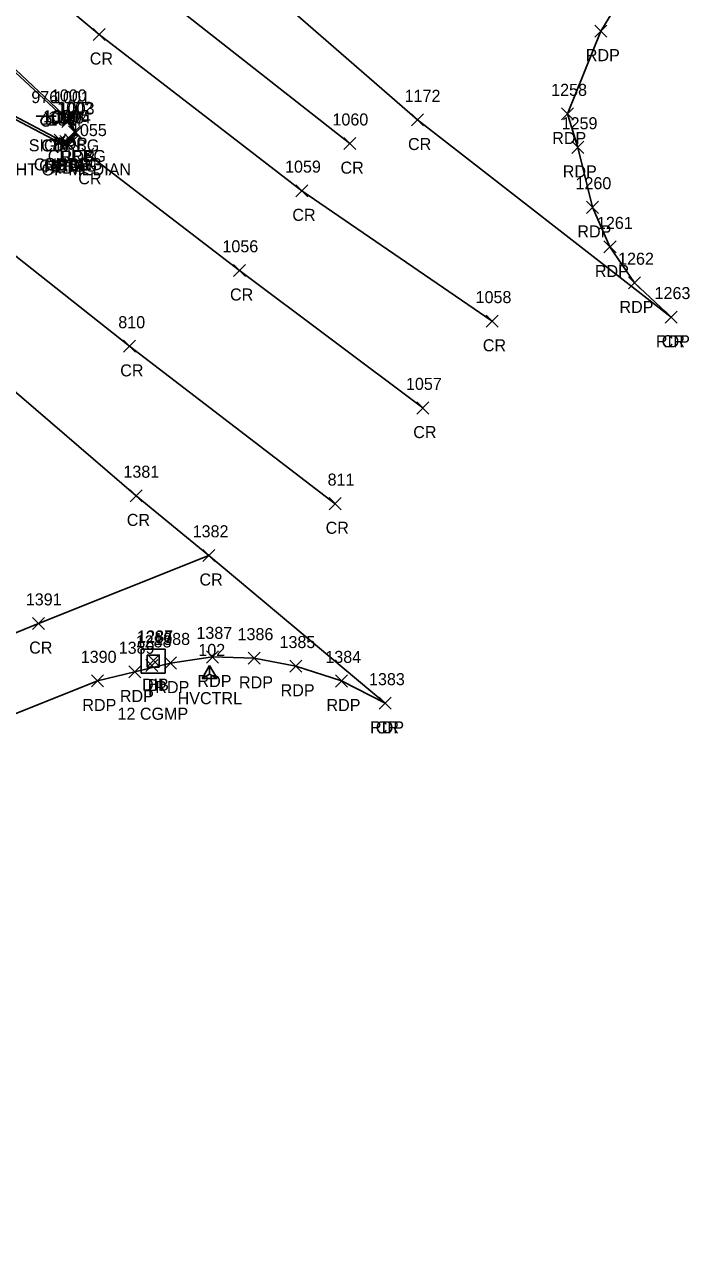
# Model space of a CAD drawing. Extents: x 1688195 to 1692013, y 424605 to 441234.
# Drawn here: x 1691903 to 1692013.4, y 439041.4 to 439243.2 of the extents above; entities that cross this region are included whole.
import ezdxf

# ---------------------------------------------------------------- set-up
doc = ezdxf.new("R2010")
doc.units = 0
for name, color, linetype in [('C_A', 7, 'Continuous'), ('C_I', 7, 'Continuous'), ('CPSM', 7, 'Continuous'), ('D_A', 7, 'Continuous'), ('D_C', 7, 'Continuous'), ('D_I', 7, 'Continuous'), ('D_TIC', 7, 'Continuous'), ('DS', 7, 'Continuous'), ('P_A', 7, 'Continuous'), ('P_I', 7, 'Continuous'), ('P_TIC', 7, 'Continuous'), ('PET', 7, 'Continuous'), ('PRC', 7, 'Continuous'), ('R_A', 7, 'Continuous'), ('R_I', 7, 'Continuous'), ('R_TIC', 7, 'Continuous'), ('RC', 7, 'Continuous'), ('S_A', 7, 'Continuous'), ('S_C', 7, 'Continuous'), ('S_I', 7, 'Continuous'), ('SSGN', 7, 'Continuous')]:
    doc.layers.add(name, color=color, linetype=linetype)

msp = doc.modelspace()

# ---------------------------------------------------------------- linework, layer by layer
at = {"layer": 'CPSM'}
for p, q in [((1691932.47, 439134.69), (1691933.72, 439136.85)), ((1691932.47, 439134.69), (1691933.72, 439136.85)), ((1691932.47, 439134.69), (1691933.72, 439136.85)), ((1691932.47, 439134.69), (1691933.72, 439136.85)), ((1691934.97, 439134.69), (1691933.72, 439136.85)), ((1691933.72, 439135.41), (1691933.72, 439136.85)), ((1691934.97, 439134.69), (1691933.72, 439136.85)), ((1691933.72, 439135.41), (1691933.72, 439136.85)), ((1691934.97, 439134.69), (1691933.72, 439136.85)), ((1691933.72, 439135.41), (1691933.72, 439136.85)), ((1691934.97, 439134.69), (1691933.72, 439136.85)), ((1691933.72, 439135.41), (1691933.72, 439136.85)), ((1691932.47, 439134.69), (1691933.72, 439135.41)), ((1691932.47, 439134.69), (1691933.72, 439135.41)), ((1691932.47, 439134.69), (1691933.72, 439135.41)), ((1691932.47, 439134.69), (1691933.72, 439135.41)), ((1691932.47, 439134.69), (1691934.97, 439134.69)), ((1691932.47, 439134.69), (1691934.97, 439134.69)), ((1691932.47, 439134.69), (1691934.97, 439134.69)), ((1691932.47, 439134.69), (1691934.97, 439134.69)), ((1691933.72, 439135.41), (1691933.72, 439135.41)), ((1691933.72, 439135.41), (1691934.97, 439134.69)), ((1691933.72, 439135.41), (1691933.72, 439135.41)), ((1691933.72, 439135.41), (1691934.97, 439134.69)), ((1691933.72, 439135.41), (1691933.72, 439135.41)), ((1691933.72, 439135.41), (1691934.97, 439134.69)), ((1691933.72, 439135.41), (1691933.72, 439135.41)), ((1691933.72, 439135.41), (1691934.97, 439134.69))]:
    msp.add_line(p, q, dxfattribs=at)
at = {"layer": 'D_TIC'}
for points in [[(1691923.39, 439136.66), (1691925.39, 439138.66)], [(1691925.39, 439136.66), (1691923.39, 439138.66)], [(1691923.14, 439135.83), (1691925.14, 439137.83)], [(1691925.14, 439135.83), (1691923.14, 439137.83)]]:
    msp.add_lwpolyline(points, dxfattribs=at)
at = {"layer": 'DS'}
for p, q in [((1691922.36, 439139.56), (1691926.36, 439139.56)), ((1691922.36, 439135.56), (1691922.36, 439139.56)), ((1691926.36, 439139.56), (1691926.36, 439135.56)), ((1691923.36, 439136.56), (1691923.36, 439138.56)), ((1691923.36, 439138.56), (1691925.36, 439138.56)), ((1691924.36, 439137.57), (1691924.36, 439137.57)), ((1691924.36, 439137.57), (1691924.36, 439137.57)), ((1691925.36, 439138.56), (1691925.36, 439136.56)), ((1691926.36, 439135.56), (1691922.36, 439135.56)), ((1691925.36, 439136.56), (1691923.36, 439136.56))]:
    msp.add_line(p, q, dxfattribs=at)
at = {"layer": 'P_TIC'}
for points in [[(1691914.39, 439240.55), (1691916.39, 439242.55)], [(1691916.39, 439240.55), (1691914.39, 439242.55)], [(1691997.71, 439241.11), (1691999.71, 439243.11)], [(1691999.71, 439241.11), (1691997.71, 439243.11)], [(1691909.3, 439226.43), (1691911.3, 439228.43)], [(1691911.3, 439226.43), (1691909.3, 439228.43)], [(1691967.23, 439226.36), (1691969.23, 439228.36)], [(1691969.23, 439226.36), (1691967.23, 439228.36)], [(1691992.13, 439227.35), (1691994.13, 439229.35)], [(1691994.13, 439227.35), (1691992.13, 439229.35)], [(1691910.52, 439224.27), (1691912.52, 439226.27)], [(1691912.52, 439224.27), (1691910.52, 439226.27)], [(1691907.76, 439222.6), (1691909.76, 439224.6)], [(1691909.76, 439222.6), (1691907.76, 439224.6)], [(1691908.81, 439222.42), (1691910.81, 439224.42)], [(1691910.81, 439222.42), (1691908.81, 439224.42)], [(1691909.89, 439222.79), (1691911.89, 439224.79)], [(1691911.89, 439222.79), (1691909.89, 439224.79)], [(1691956.02, 439222.44), (1691958.02, 439224.44)], [(1691958.02, 439222.44), (1691956.02, 439224.44)], [(1691993.88, 439221.81), (1691995.88, 439223.81)], [(1691995.88, 439221.81), (1691993.88, 439223.81)], [(1691912.48, 439220.68), (1691914.48, 439222.68)], [(1691914.48, 439220.68), (1691912.48, 439222.68)], [(1691948.03, 439214.61), (1691950.03, 439216.61)], [(1691950.03, 439214.61), (1691948.03, 439216.61)], [(1691996.3, 439211.86), (1691998.3, 439213.86)], [(1691998.3, 439211.86), (1691996.3, 439213.86)], [(1691999.21, 439205.28), (1692001.21, 439207.28)], [(1692001.21, 439205.28), (1691999.21, 439207.28)], [(1691937.67, 439201.39), (1691939.67, 439203.39)], [(1691939.67, 439201.39), (1691937.67, 439203.39)], [(1692003.29, 439199.33), (1692005.29, 439201.33)], [(1692005.29, 439199.33), (1692003.29, 439201.33)], [(1692009.35, 439193.63), (1692011.35, 439195.63)], [(1692011.35, 439193.63), (1692009.35, 439195.63)], [(1692009.35, 439193.63), (1692011.35, 439195.63)], [(1692011.35, 439193.63), (1692009.35, 439195.63)], [(1691979.66, 439192.96), (1691981.66, 439194.96)], [(1691981.66, 439192.96), (1691979.66, 439194.96)], [(1691919.44, 439188.8), (1691921.44, 439190.8)], [(1691921.44, 439188.8), (1691919.44, 439190.8)], [(1691968.11, 439178.56), (1691970.11, 439180.56)], [(1691970.11, 439178.56), (1691968.11, 439180.56)], [(1691920.53, 439163.99), (1691922.53, 439165.99)], [(1691922.53, 439163.99), (1691920.53, 439165.99)], [(1691953.55, 439162.68), (1691955.55, 439164.68)], [(1691955.55, 439162.68), (1691953.55, 439164.68)], [(1691932.61, 439154.1), (1691934.61, 439156.1)], [(1691934.61, 439154.1), (1691932.61, 439156.1)], [(1691932.61, 439154.1), (1691934.61, 439156.1)], [(1691934.61, 439154.1), (1691932.61, 439156.1)], [(1691904.33, 439142.8), (1691906.33, 439144.8)], [(1691906.33, 439142.8), (1691904.33, 439144.8)], [(1691933.22, 439137.24), (1691935.22, 439139.24)], [(1691935.22, 439137.24), (1691933.22, 439139.24)], [(1691940.11, 439137.03), (1691942.11, 439139.03)], [(1691942.11, 439137.03), (1691940.11, 439139.03)], [(1691920.33, 439134.77), (1691922.33, 439136.77)], [(1691922.33, 439134.77), (1691920.33, 439136.77)], [(1691926.22, 439136.24), (1691928.22, 439138.24)], [(1691928.22, 439136.24), (1691926.22, 439138.24)], [(1691947.02, 439135.72), (1691949.02, 439137.72)], [(1691949.02, 439135.72), (1691947.02, 439137.72)], [(1691914.1, 439133.27), (1691916.1, 439135.27)], [(1691916.1, 439133.27), (1691914.1, 439135.27)], [(1691954.64, 439133.26), (1691956.64, 439135.26)], [(1691956.64, 439133.26), (1691954.64, 439135.26)], [(1691961.88, 439129.56), (1691963.88, 439131.56)], [(1691963.88, 439129.56), (1691961.88, 439131.56)], [(1691961.88, 439129.56), (1691963.88, 439131.56)], [(1691963.88, 439129.56), (1691961.88, 439131.56)]]:
    msp.add_lwpolyline(points, dxfattribs=at)
at = {"layer": 'PET'}
for points in [[(1691800.95, 439315.05), (1691800.71, 439316.53), (1691801.54, 439317.59), (1691803.01, 439317.75), (1691817.06, 439309.7), (1691828.51, 439300.65), (1691844.68, 439285.42), (1691865.17, 439267.39), (1691884.85, 439250.83), (1691897.53, 439239.42), (1691910.3, 439227.43), (1691911.52, 439225.27), (1691910.89, 439223.79), (1691909.81, 439223.42), (1691908.76, 439223.6), (1691890.09, 439233.4), (1691870.38, 439245.17), (1691862.38, 439250.39), (1691860.03, 439251.8), (1691851, 439258.94), (1691829.1, 439279.04), (1691821.39, 439286.91), (1691810.78, 439300.43)], [(1692007.49, 439254.05), (1692002.68, 439248.67), (1691998.71, 439242.11), (1691993.13, 439228.35), (1691994.88, 439222.81), (1691997.3, 439212.86), (1692000.21, 439206.28), (1692004.29, 439200.33), (1692010.35, 439194.63)], [(1691962.88, 439130.56), (1691955.64, 439134.26), (1691948.02, 439136.72), (1691941.11, 439138.03), (1691934.22, 439138.24), (1691927.22, 439137.24), (1691921.33, 439135.77), (1691915.1, 439134.27), (1691873.49, 439117.66), (1691865.77, 439114.89), (1691827.16, 439101.41), (1691792.77, 439088.6), (1691761.14, 439076.62), (1691734.19, 439066.23), (1691708.14, 439056.57), (1691672.86, 439042.9), (1691649.54, 439032.89)]]:
    msp.add_lwpolyline(points, dxfattribs=at)
at = {"layer": 'PRC'}
for points in [[(1691980.66, 439193.96), (1691949.03, 439215.61), (1691915.39, 439241.55), (1691887.2, 439265.05), (1691850.38, 439298.07), (1691824.99, 439321.73), (1691796.94, 439350.89), (1691771.5, 439379.22), (1691742.05, 439414.41)], [(1691713.18, 439386.48), (1691737.31, 439357.71), (1691761.17, 439330.74), (1691784.31, 439305.52), (1691812.13, 439278.2), (1691838.3, 439254.51), (1691867.44, 439230.25), (1691889.26, 439214.41), (1691920.44, 439189.8), (1691954.55, 439163.68)], [(1691957.02, 439223.44), (1691923.55, 439249.72), (1691894.35, 439275.35), (1691862.96, 439302.59), (1691832.42, 439330.49), (1691805.17, 439357.5)], [(1691939.54, 439252.36), (1691968.23, 439227.36), (1692010.35, 439194.63)], [(1691913.48, 439221.68), (1691938.67, 439202.39), (1691969.11, 439179.56)], [(1691888.13, 439193.66), (1691921.53, 439164.99), (1691933.61, 439155.1), (1691905.33, 439143.8), (1691864.7, 439127.18), (1691822.78, 439112.3), (1691787.26, 439099.58), (1691756.92, 439088.3), (1691729.19, 439077.85), (1691704.03, 439068.3), (1691667.7, 439053.5), (1691645.71, 439043.49), (1691628.46, 439034.88), (1691608.73, 439022.92), (1691585.22, 439006.39), (1691574.92, 438998.75), (1691559.84, 438985.93), (1691543.5, 438970.76), (1691518.61, 438946.02), (1691478.27, 438903.21), (1691447.81, 438870), (1691426.94, 438847.45)], [(1691933.61, 439155.1), (1691962.88, 439130.56)]]:
    msp.add_lwpolyline(points, dxfattribs=at)
at = {"layer": 'R_TIC'}
for points in [[(1691909.16, 439226.13), (1691911.16, 439228.13)], [(1691911.16, 439226.13), (1691909.16, 439228.13)], [(1691910.27, 439224.37), (1691912.27, 439226.37)], [(1691912.27, 439224.37), (1691910.27, 439226.37)], [(1691907.93, 439222.98), (1691909.93, 439224.98)], [(1691909.93, 439222.98), (1691907.93, 439224.98)], [(1691908.84, 439222.78), (1691910.84, 439224.78)], [(1691910.84, 439222.78), (1691908.84, 439224.78)], [(1691909.65, 439223.03), (1691911.65, 439225.03)], [(1691911.65, 439223.03), (1691909.65, 439225.03)]]:
    msp.add_lwpolyline(points, dxfattribs=at)
at = {"layer": 'RC'}
msp.add_lwpolyline([(1691801.25, 439315.04), (1691801.11, 439316.33), (1691801.76, 439317.38), (1691802.82, 439317.35), (1691816.87, 439309.41), (1691828.25, 439300.3), (1691844.42, 439285.11), (1691865.02, 439267.12), (1691884.74, 439250.47), (1691897.46, 439238.93), (1691910.16, 439227.13), (1691911.27, 439225.37), (1691910.65, 439224.03), (1691909.84, 439223.78), (1691908.93, 439223.98), (1691890.41, 439233.73), (1691870.59, 439245.45), (1691863.21, 439250.36), (1691862.38, 439250.39)], dxfattribs=at)
at = {"layer": 'SSGN'}
for p, q in [((1691904.91, 439228.01), (1691908.24, 439228.01)), ((1691906.55, 439227.17), (1691906.55, 439227.17))]:
    msp.add_line(p, q, dxfattribs=at)
msp.add_circle((1691906.55, 439227.17), 0.833, dxfattribs=at)

# ---------------------------------------------------------------- texts
at = {"layer": 'C_A'}
msp.add_text('HVCTRL', height=2, dxfattribs=at).set_placement((1691928.41, 439130.41))
msp.add_text('HVCTRL', height=2, dxfattribs=at).set_placement((1691928.41, 439130.41))
msp.add_text('HVCTRL', height=2, dxfattribs=at).set_placement((1691928.41, 439130.41))
msp.add_text('HVCTRL', height=2, dxfattribs=at).set_placement((1691928.41, 439130.41))
at = {"layer": 'C_I'}
msp.add_text('102', height=2, dxfattribs=at).set_placement((1691931.85, 439138.41))
msp.add_text('102', height=2, dxfattribs=at).set_placement((1691931.85, 439138.41))
msp.add_text('102', height=2, dxfattribs=at).set_placement((1691931.85, 439138.41))
msp.add_text('102', height=2, dxfattribs=at).set_placement((1691931.85, 439138.41))
at = {"layer": 'D_A'}
for s, p in [('DIB', (1691922.5, 439132.66)), ('DI', (1691923.42, 439132.57)), ('P', (1691923.52, 439131.83))]:
    msp.add_text(s, height=2, dxfattribs=at).set_placement(p)
at = {"layer": 'D_C'}
msp.add_text('12 CGMP', height=2, dxfattribs=at).set_placement((1691918.43, 439127.83))
at = {"layer": 'D_I'}
for s, p in [('1287', (1691921.7, 439140.66)), ('1288', (1691921.45, 439139.83)), ('1286', (1691921.61, 439140.57))]:
    msp.add_text(s, height=2, dxfattribs=at).set_placement(p)
at = {"layer": 'P_A'}
for s, p in [('CR', (1691913.82, 439236.55)), ('RDP', (1691996.2, 439237.11)), ('RDP', (1691907.79, 439222.43)), ('CR', (1691966.67, 439222.36)), ('RDP', (1691990.62, 439223.35)), ('RDP', (1691909.01, 439220.27)), ('RDP', (1691906.25, 439218.6)), ('RDP', (1691907.3, 439218.42)), ('RDP', (1691908.38, 439218.79)), ('CR', (1691955.46, 439218.44)), ('RDP', (1691992.37, 439217.81)), ('CR', (1691911.91, 439216.68)), ('CR', (1691947.46, 439210.61)), ('RDP', (1691994.79, 439207.86)), ('RDP', (1691997.7, 439201.28)), ('CR', (1691937.11, 439197.39)), ('RDP', (1692001.78, 439195.33)), ('RDP', (1692007.84, 439189.63)), ('CR', (1692008.79, 439189.63)), ('CR', (1691979.09, 439188.96)), ('CR', (1691918.88, 439184.8)), ('CR', (1691967.54, 439174.56)), ('CR', (1691919.97, 439159.99)), ('CR', (1691952.99, 439158.68)), ('CR', (1691932.04, 439150.1)), ('CR', (1691932.04, 439150.1)), ('CR', (1691903.76, 439138.8)), ('RDP', (1691931.71, 439133.24)), ('RDP', (1691938.6, 439133.03)), ('RDP', (1691918.82, 439130.77)), ('RDP', (1691924.71, 439132.24)), ('RDP', (1691945.51, 439131.72)), ('RDP', (1691912.59, 439129.27)), ('RDP', (1691953.13, 439129.26)), ('RDP', (1691960.37, 439125.56)), ('CR', (1691961.32, 439125.56))]:
    msp.add_text(s, height=2, dxfattribs=at).set_placement(p)
at = {"layer": 'P_I'}
for s, p in [('1000', (1691907.36, 439230.43)), ('1172', (1691966.11, 439230.36)), ('1258', (1691990.44, 439231.35)), ('1003', (1691908.67, 439228.27)), ('1008', (1691905.91, 439226.6)), ('1007', (1691906.96, 439226.42)), ('1004', (1691908.04, 439226.79)), ('1060', (1691954.12, 439226.44)), ('1259', (1691992.18, 439225.81)), ('1055', (1691910.7, 439224.68)), ('1059', (1691946.25, 439218.61)), ('1260', (1691994.48, 439215.86)), ('1261', (1691998.04, 439209.28)), ('1056', (1691935.85, 439205.39)), ('1262', (1692001.55, 439203.33)), ('1263', (1692007.61, 439197.63)), ('1263', (1692007.61, 439197.63)), ('1058', (1691977.89, 439196.96)), ('810', (1691918.56, 439192.8)), ('1057', (1691966.33, 439182.56)), ('1381', (1691919.41, 439167.99)), ('811', (1691953.32, 439166.68)), ('1382', (1691930.91, 439158.1)), ('1382', (1691930.91, 439158.1)), ('1391', (1691903.2, 439146.8)), ('1387', (1691931.53, 439141.24)), ('1386', (1691938.36, 439141.03)), ('1389', (1691918.63, 439138.77)), ('1388', (1691924.53, 439140.24)), ('1385', (1691945.33, 439139.72)), ('1390', (1691912.32, 439137.27)), ('1384', (1691952.94, 439137.26)), ('1383', (1691960.19, 439133.56)), ('1383', (1691960.19, 439133.56))]:
    msp.add_text(s, height=2, dxfattribs=at).set_placement(p)
at = {"layer": 'R_A'}
for p in [(1691905.75, 439222.13), (1691906.85, 439220.37), (1691904.52, 439218.98), (1691905.42, 439218.78), (1691906.23, 439219.03)]:
    msp.add_text('CURBG', height=2, dxfattribs=at).set_placement(p)
at = {"layer": 'R_I'}
for s, p in [('1001', (1691907.88, 439230.13)), ('1002', (1691908.42, 439228.37)), ('1009', (1691906.07, 439226.98)), ('1006', (1691906.93, 439226.78)), ('1005', (1691907.8, 439227.03))]:
    msp.add_text(s, height=2, dxfattribs=at).set_placement(p)
at = {"layer": 'S_A'}
msp.add_text('SIGN', height=2, dxfattribs=at).set_placement((1691903.69, 439222.15))
at = {"layer": 'S_C'}
msp.add_text('STAY RIGHT OF MEDIAN', height=2, dxfattribs=at).set_placement((1691889.03, 439218.15))
at = {"layer": 'S_I'}
msp.add_text('976', height=2, dxfattribs=at).set_placement((1691904.12, 439230.15))

doc.saveas('drawing.dxf')
